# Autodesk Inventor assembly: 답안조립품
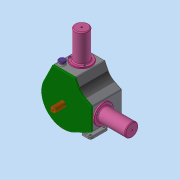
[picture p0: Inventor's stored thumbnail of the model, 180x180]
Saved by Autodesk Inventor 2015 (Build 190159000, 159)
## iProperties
Created: 2022-01
Part Number: 답안조립품
Document SubType Name: Assembly
Designer: user
Mass: 3748.68 g
Surface Area: 4101.78 cm^2
Volume: 1119.43 cm^3
Density: 3.34872 g/cm^3
Author: user
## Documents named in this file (13)
- C:\Users\user\Desktop\620117V1004\답안조립품.iam
- C:\Users\user\Desktop\620117V1004\너트 M3.ipt
- C:\Users\user\Desktop\620117V1004\베어링 20 x 37 x 9.ipt
- C:\Users\user\Desktop\620117V1004\본체.ipt
- C:\Users\user\Desktop\620117V1004\볼트 M3 x 12.ipt
- C:\Users\user\Desktop\620117V1004\실린더.ipt
- C:\Users\user\Desktop\620117V1004\앞커버.ipt
- C:\Users\user\Desktop\620117V1004\축.ipt
- C:\Users\user\Desktop\620117V1004\측정게이지.ipt
- C:\Users\user\Desktop\620117V1004\커넥팅로드 캡.ipt
- C:\Users\user\Desktop\620117V1004\커넥팅로드.ipt
- C:\Users\user\Desktop\620117V1004\피스톤 핀.ipt
- C:\Users\user\Desktop\620117V1004\피스톤.ipt
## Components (4 placed, 2 different names)
1. 피스톤 핀:1
2. 피스톤:1
3. 피스톤 핀:2
4. 피스톤:2
